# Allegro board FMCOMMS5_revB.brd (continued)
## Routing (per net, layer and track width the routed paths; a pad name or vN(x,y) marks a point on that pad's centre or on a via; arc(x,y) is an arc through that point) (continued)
VDD_AMP_5V: length 43.5
  TOP w0.394: E509.2 C547.2 C548.2 46.72,51.15 47.09,50.79 58.58,50.79 v1(59.37,51.57)
  BOTTOM w0.394: L210.2 13.29,53.53 C254.2 C252.1 C253.2 16.67,54.38 15.19,55.86 v1(10.12,55.86) v1(9.25,55.86) v1(8.37,55.86) ; v1(7.08,87.49) C103.1 C113.2 C112.2 11.3,87.49 L111.2 ; C212.2 C203.1 C213.2 ; L110.2 54.74,124.14 C152.1 C154.2 C153.2 v1(54.75,120.9) ; C213.2 50.99,9.03 v1(51.19,9.23) ; C213.2 50.11,9.04 L211.2 v1(51.12,10.49)
  vias: v1(28.48,8.57) v1(30.23,8.55) v1(31.88,8.55) v1(38.64,8.57) v1(40.04,8.57) v1(41.44,8.57) v1(88.05,39.58) v1(88.05,38.57) v1(88.02,37.52)
VDD_EXT_LO_3P3: length 38
  TOP w0.305: U302.4 24.95,67.48 v3(25.2,67.22) ; v3(28.76,72.73) 28.43,72.4 U302.16 ; v3(37.32,69.15) 37.09,69.38 U307.13 ; C335.1 C334.1 37.93,70.7 38,70.77 C333.1 ; U302.27 v3(21.65,71.4) 21.28,71.4 20.66,72.02 C307.1 ; U307.16 36.99,70.88 v3(37.27,70.6) 37.05,70.38 U307.15 ; v3(30.79,69.08) R317.2 29.7,69.08 29.57,69.2 C308.1 28.68,69.2 28.49,69.4 U302.10 ; v3(31.07,71.36) 30.92,71.21 R318.2
  TOP w0.394: v3(37.32,69.15) C335.1 37.93,68.44 40.44,65.93 40.44,51.63 38.96,50.14 v3(38.55,50.14) ; C306.1 29.12,73.09 v3(28.76,72.73)
  BOTTOM w0.394: R303.1 v3(38.55,50.14)
  vias: v3(70.21,71.13) v3(70.21,70.55) v3(72.78,71.51) v3(72.78,70.8)
VDD_INTERFACE_A: length 50.2
  TOP w0.203: R103.1 26.92,114.77 27.78,113.9 27.78,113.9 27.89,113.8 28.01,113.68 28.01,113.31 27.78,113.09 27.78,112.77 28.01,112.55 28.01,112.18 27.78,111.95 27.78,111.53 28.51,110.81 v2(29.73,110.81)
  TOP w0.305: C612.1 31.91,109.74 31.48,109.74 C613.1 31.06,110.16 30.4,110.16 v2(30.39,110.15) v2(30.03,110.5) v2(29.73,110.81)
  TOP w0.394: v1(53.69,76.66) 53.61,76.74 R511.2 v1(54.19,77.41) ; C612.1 35.19,106.46 v1(35.19,100.01) v1(35.19,99.33) v1(35.19,98.54) ; R507.2 v3(54.2,84.23)
  BOTTOM w0.254: v2(30.39,110.15) v2(30.03,110.5) v2(29.73,110.81) 29.3,111.23 U101.H12
  BOTTOM w0.305: R403.1 79.87,117.14 ; 79.87,121.03 R407.1 79.87,122.05
  BOTTOM w0.394: 79.87,117.14 79.87,121.03 ; v1(66.91,126.28) v1(67.75,126.28) 78.82,126.28 79.87,125.23 79.87,122.05 ; 49.61,72.68 49.6,72.69 C610.1 48.48,72.7 C611.1
  vias: v1(42.71,77.98) v1(44.65,77.35) v1(49.48,77.8) v1(52.35,77.8)
VDD_INTERFACE_B: length 23.6
  TOP w0.229: R203.1 23.25,28.22 23.25,28.41 23.98,29.14 23.98,29.14 26.62,31.78
  TOP w0.305: v1(53.93,69.53) 53.93,69.91 53.65,70.19 R519.2
  TOP w0.394: v2(27.62,30.54) 27.57,30.54 C617.1 26.62,31.49 C616.1 26.2,32.47 v3(25.59,33.08) v3(25.59,33.67) ; R515.2 53.65,64.33 v1(53.88,64.55)
  BOTTOM w0.254: U201.H12 27.2,30.11 v2(27.62,30.54)
  BOTTOM w0.305: 83.37,119.01 R405.1
  BOTTOM w0.394: v1(88.37,119.75) 87.61,120.51 85.71,120.51 84.21,119.01 83.37,119.01 ; v1(49.99,70.24) 49.99,70.42 49.61,70.8 E514.2 49.6,71.32 C614.1 48.46,71.31 C615.1 46.33,71.31
  vias: v1(71.36,61.48) v1(72.3,61.23) v1(73.13,61.23) v1(74.07,61.3) v3(43.44,70.46) v3(44.21,70.47) v3(44.91,70.48) v3(49.28,70.52)
VDD_LNA_3P3: length 27.6
  BOTTOM w0.394: v3(25.04,11.13) C250.1 R212.2 ; v3(6.71,127.34) 7.24,127.87 C148.1 R109.2 ; E504.1 62.6,67.99 C513.1 60.27,67.99 C512.1 58.64,67.99 58.63,68 C510.1 58.12,68.01 C511.1 57.06,66.86 v1(63.6,60.31) v1(64.4,60.31) v1(65.74,60.31) ; R209.2 C248.1 v3(11.11,10.74) ; R112.2 C150.1 v3(11.93,114.91)
  vias: v1(22.45,12.58) v1(22.5,13.82) v1(24.28,12.52) v1(24.33,13.77) v1(25.9,13.85) v1(25.95,12.52)
VDD_RF_SW: length 72.9
  L5_SIG w0.124: v3(23.77,63.61) 23.77,63.53 24.32,62.98 25.36,62.98 25.48,63.11 31.15,63.11 31.4,62.85 32.62,62.85 35.14,65.37 47.45,65.37 50.99,68.9 55.61,68.9 v3(56.95,70.24)
  BOTTOM w0.305: U305.1 19.06,80.46 18.69,80.09 C340.1 16.47,79.64 16.6,79.51 C341.1 16.6,78.8 16.62,78.79 C342.1 ; U306.1 20.94,60.59 21.39,61.05 C343.1 23.68,61.61 23.75,61.68 C345.1 23.75,62.42 23.77,62.44 C344.1 v3(23.77,63.61)
  BOTTOM w0.394: v3(56.95,70.24) 56.85,70.35 C641.1 56.14,70.34 C640.1 55.07,70.35 C639.1 53.6,70.35 53.42,70.52 E1.2 52.92,70.43 53.04,70.31 53.04,69.76 52.92,69.64 52.92,69.3 C638.1 ; v3(23.77,63.61) 22.44,64.95 22.44,65.6 22.94,66.1 22.94,67.68 21.74,68.88 20.85,68.88 20.28,69.46 20.28,70.37 18.17,72.48 18.17,76.39 16.62,77.94 C342.1
VDD_VCO_5V: length 29.7
  TOP w0.305: v1(26.91,77.53) C323.2 26.91,76.19 26.9,76.18 C320.2 26.9,74.76 C309.2 26.89,73.93 ; 26.89,73.93 26.95,73.88 U302.17 ; 26.89,73.93 26.87,73.95 26.2,73.95 25.95,73.71 U302.19 ; v3(25.62,65.39) C317.2 25.62,66.69 25.95,67.03 U302.6
  TOP w0.394: E507.2 47.33,53.89 47.25,53.96 C543.2 C544.2 45.71,54.68 44.64,55.76 v1(42.02,55.76)
  BOTTOM w0.394: v3(25.62,65.39) 25.73,65.5 25.73,67.65 24.49,68.89 24.49,75.12 v1(26.91,77.53)
VDDA_GPO_A: length 15.4
  TOP w0.394: v2(23.64,109.66) 23.63,109.66 C520.1 23.26,109.29 C521.1
  L8_PWR w0.394: 28.61,103.77 26.3,106.08 25,106.08 23.64,107.44 v2(23.64,109.66)
  BOTTOM w0.254: 23.64,109.67 U101.B8
  BOTTOM w0.305: v2(23.64,109.66) 23.64,109.67
  BOTTOM w0.394: E501.2 62.82,73.48 62.8,73.46 C518.1 61.58,73.46 61.56,73.44 C519.1 60.26,73.88 60.74,74.36 v3(61.09,74.36)
VDDA_GPO_B: length 27.3
  TOP w0.394: v2(28.77,24.45) 29.13,24.09 C524.1 29.88,23.32 C525.1 29.88,23.32 33.33,19.88 36.3,19.88 40.95,24.52 v1(40.95,31.31) v1(41.74,31.31)
  BOTTOM w0.254: 28.76,24.45 U201.B8
  BOTTOM w0.305: v2(28.77,24.45) 28.76,24.45
  BOTTOM w0.394: E503.2 63.45,70.16 C523.1 62.33,70.17 C522.1 60.38,70.17 v1(60.26,70.04)
1P3_DIG_A: length 91.9
  TOP w0.305: C589.1 28.16,109.5 v2(28.16,109.53)
  TOP w0.394: v3(32.39,114.72) v3(33.13,114.72) 33.51,114.34 v3(33.84,114.34) 34.4,114.34 L102.1 36.69,114.42 C119.1 36.71,114.42 C118.2 ; C135.1 28.86,120.79 C134.2 ; C134.2 28.41,119.53 v2(28.57,119.53) ; C134.2 27.29,119.22 27.29,119.16 27.29,119.02 26.7,118.43 26.48,118.43 C585.1 26.12,118.07 26.12,117.67 v2(25.9,117.45) ; v3(28.99,117.69) 29.23,117.69 L104.1 ; v1(14.51,117.28) v1(14.51,118.02) v1(14.51,118.73) 14.92,118.73 15.4,118.25 16.36,118.25 C120.2 17.39,117.23 17.39,117.22 C121.1 17.99,116.58 C592.1 18.75,115.78 C593.1 19.77,114.77 20.38,114.77 20.44,114.76 20.49,114.75 20.68,114.75 v2(20.81,114.62) 20.81,114.62 v2(21.38,114.06) v2(21.94,114.62) ; v1(24.7,100.29) v1(25.41,100.29) v1(26.09,100.29) 30.28,100.29 32.98,102.98 32.98,104.71 32.39,105.29 C587.1 31.65,106.04 C586.1 30.87,106.79 C591.1 30.57,107.12 30.31,107.12 C590.1 29.65,107.78 29.65,108.04 C588.1 29.29,108.37 C589.1
  BOTTOM w0.254: v2(20.81,114.62) U101.D2 ; v2(21.94,114.62) U101.E3 ; v2(21.38,114.06) 21.7,114.06 U101.D3 ; v2(28.16,109.53) U101.F12 ; U101.K4 v2(25.9,117.45)
  BOTTOM w0.305: v3(28.99,117.69) 28.99,119.12 28.57,119.53 v2(28.57,119.53) 28.57,119.86 L103.1
  BOTTOM w0.394: L105.1 v1(17.34,108.63) ; v3(42.39,75.95) v3(42.39,75.26) v3(42.39,74.6) 41.59,73.8 41.59,68.72 36.9,64.03 36.9,56.95 41.34,52.51 41.35,52.47 41.35,45.11 41.05,44.81 R325.1 ; L101.1 33.1,115.87 33.1,114.74 v3(33.13,114.72) ; 22.51,105.27 v1(21.61,104.37)
1P3_DIG_B: length 73.8
  TOP w0.356: C220.2 25.08,19.29 C221.1 24.68,19.7 24.65,19.7 24.3,20.05
  TOP w0.394: C218.2 24.66,34.75 24.6,34.75 C219.1 23.64,35.71 23.59,35.71 L202.1 22.88,36.4 21.8,37.48 v1(21.8,39.59) 21.34,39.59 v1(21.01,39.92) ; v2(28.9,28.98) 28.93,28.98 C634.1 29.31,29.38 C635.1 ; v1(23.78,39.18) v1(24.47,39.18) 27.52,36.13 27.52,32.7 27.83,32.39 C636.1 28.57,31.64 C234.2 29.35,30.89 C629.1 30.06,30.16 C635.1 ; C635.1 30.42,30.49 30.67,30.49 C632.1 ; v2(20.98,26.71) 20.98,27.1 C630.1 20.41,27.67 19.7,27.67 19.27,28.1 C633.1 18.88,28.49 18.83,28.49 C637.1 18.12,29.2 18.11,29.2 C235.1 16.48,30.82 v3(16.19,30.82) ; v3(24.06,16.47) v3(24.75,16.47) 25.05,16.47 26.17,17.59 26.17,18.2 C220.2 ; 24.3,20.05 24.23,20.12 24.23,20.52 23.8,20.95 C628.1 23.81,21.08 v2(23.81,21.62) 23.81,21.62 v2(24.37,22.19) v2(23.81,22.75) ; v3(20.74,29.8) 20.74,30.04 L204.1
  BOTTOM w0.254: v2(28.9,28.98) U201.F12 ; U201.K4 v2(20.98,26.71) ; v2(23.81,21.62) U201.D2 ; U201.E3 v2(23.81,22.75) ; U201.D3 v2(24.37,22.19)
  BOTTOM w0.394: L205.1 29.29,18.66 29.29,17.74 v1(29.14,17.59) ; v1(35.09,20.69) 35.09,21.39 33.16,23.32 ; v1(25.94,49.54) 26.22,49.26 30.82,49.26 32.14,47.94 32.14,47.1 33.68,45.56 34.91,45.56 35.52,44.95 37.22,44.95 38.12,44.05 R327.1 ; 17.84,30.11 17.13,30.82 v3(16.19,30.82) ; 22.11,34.37 22.09,34.37 21.34,35.12 21.34,37.91 21.8,38.37 v1(21.8,39.59) 21.34,39.59 v1(21.01,39.92)
  vias: v3(42.43,69.16) v3(42.43,68.48) v3(42.43,67.82)
1P3_RF_A: length 83.7
  TOP w0.305: v2(24.21,109.1) v2(24.77,108.53)
  TOP w0.394: 24.77,117.45 v2(25.34,118.02) 25.34,118.86 25.18,119.02 C572.1 25.18,119.9 25.43,120.15 C574.1 25.43,121.65 C573.1 25.43,122.47 v3(23.27,124.63) v3(23.76,125.11) v3(24.24,125.59) ; 24.77,117.45 24.77,117.85 C575.1 ; 24.77,117.45 v2(24.77,117.45) ; v2(21.38,115.19) v2(21.94,115.76) 21.94,115.8 C570.1 21.06,116.67 21.06,116.73 C571.1 20.48,116.98 19.46,118 17.66,118 16.47,119.19 15.93,119.19 v3(15.78,119.34) v3(16.16,119.72) ; v2(24.21,109.1) 24.21,108.74 C569.1 23.62,108.15 23.56,108.15 C568.1
  L8_PWR w0.394: v1(33.08,100.5) 33.08,101 v1(31.45,102.63) 31.07,102.63 26.91,106.79 25.31,106.79 24.77,107.33 v2(24.77,108.53) v2(24.21,109.1)
  BOTTOM w0.254: v2(21.94,115.76) U101.F2 ; v2(24.77,117.45) 24.77,117.45 U101.J3 ; v2(24.77,108.53) 24.77,108.54 U101.B10 ; U101.B9 24.2,109.1 v2(24.21,109.1) ; v2(21.38,115.19) U101.E2 ; U101.K3 v2(25.34,118.02)
  BOTTOM w0.394: R326.1 39.89,44.67 40.6,45.38 40.6,52.21 35.29,57.52 35.29,63.89 40.47,69.08 40.47,79.49 v3(42.4,81.42) v3(42.4,82.08) v3(42.4,82.77)
1P3_RF_B: length 72.3
  TOP w0.305: v2(29.33,25.02) v2(29.9,25.59) ; v2(20.98,25.58) 20.56,25.58 C607.1 20.21,25.27 20.04,25.11 19.65,25.11 19.49,25.27 19.46,25.27 19.4,25.33 19.37,25.33 C608.1
  TOP w0.394: v3(23.02,16.47) v3(22.28,16.47) v3(21.63,16.47) 21.63,19.72 21.27,20.08 21.27,21.44 C516.1 21.87,22.04 21.92,22.04 C515.1 22.63,22.75 v2(22.67,22.75) v2(23.24,22.19) ; v2(29.33,25.02) 29.69,25.02 C545.1 30.2,24.51 30.2,24.46 C609.1 30.67,23.98 31.83,22.82 31.91,22.82 33.21,21.53 36.63,21.53 39.99,24.88 39.99,37.2 v1(42.12,39.33) v1(43.09,39.33) v1(44.1,39.33) ; C608.1 18.28,24.93 C546.1 17.57,24.24 C517.1 17.55,24.24 16.52,23.2 v3(14.79,23.2) 14.77,23.2 v3(14.33,23.63) v3(13.88,24.09) ; v2(20.41,26.15) v2(20.98,25.58)
  BOTTOM w0.254: v2(29.9,25.59) 29.89,25.58 U201.B10 ; v2(22.67,22.75) U201.F2 ; U201.K3 v2(20.41,26.15) ; U201.B9 29.33,25.02 v2(29.33,25.02) ; v2(20.98,25.58) U201.J3 ; v2(23.24,22.19) U201.E2
  BOTTOM w0.394: TP307.1 25,50.86 25,49.24 27.84,46.4 31.47,46.4 32.98,44.89 34.68,44.89 35.7,43.87 R310.1 35.24,43.3 34.96,43.01 34.96,40.98 35.01,40.93
  vias: v3(42.52,62.36) v3(42.52,61.67) v3(42.52,61.01)
1P3_TX2A_A: length 0.8
  BOTTOM w0.254: U101.A9 U101.A10
1P3_TX2A_B: length 0.8
  BOTTOM w0.254: U201.A9 U201.A10
1P8_CLK: length 82.4
  TOP w0.203: U301.13 v3(18.2,68.24) ; U301.16 v3(18.2,69.74)
  TOP w0.305: U301.10 v3(15.51,66.54) ; U301.22 15.01,72.53 15,72.53 C303.1 ; U301.5 12.53,68.74 v3(12.28,69) 12.52,69.24 U301.4 ; U301.19 v3(17.21,71.49)
  TOP w0.394: Y301.4 Y301.1 C347.1 8.71,75.81 C346.1 8.71,77.55 v1(9.28,78.12) ; C303.1 14.99,73.09 C304.1 C305.1 14.99,75.65 v1(14.69,75.96)
  L5_SIG w0.635: v3(15.51,66.54) 17.59,64.45 28.53,64.45 31.05,66.97 44.71,66.97 v3(45.37,67.63)
  BOTTOM w0.394: C559.1 49.85,67.62 49.84,67.63 C558.1 48.19,67.63 C557.1 48.19,67.25 ; v3(15.51,66.54) 16.5,66.54 v3(18.2,68.24) v3(18.2,69.74) 18.2,70.5 v3(17.21,71.49) 17.21,72.4 15.86,73.75 15.86,74.79 v1(14.69,75.96) 14.69,71.95 13.66,70.92 13.66,69.55 13.11,69 v3(12.28,69) 9.28,72 v1(9.28,78.12)
1P8V: length 42.3
  TOP w0.305: C576.1 56.34,75.63 ; U506.3 55.19,60.74 ; v3(53.91,71.84) 53.86,71.89 53.86,72 53.76,72.1 U505.16 U505.15 ; U505.1 55.17,73.03 ; U504.3 55.18,81.15 ; U504.2 55.18,80.5 ; v1(54.72,65.6) 54.07,66.24 U507.1 ; 55.27,59.44 U506.1 53.95,58.72 ; 53.02,57.56 U506.16 53.74,58.51 ; U504.1 55.18,79.85 ; 53.95,65.32 U507.16 U507.15 ; U505.3 55.17,74.33 ; U507.2 55.21,66.89 ; U506.15 52.37,57.6 ; U504.15 U504.16 53.92,78.92 ; C620.1 56.29,77.38 ; U506.2 55.19,60.09 ; U505.2 55.17,73.68 ; U507.3 55.21,67.54
  TOP w0.394: C555.1 57.76,87.36 ; C560.1 57.76,89.75 ; R506.2 64.73,89.4 ; C594.1 53.09,57.01 ; C556.1 57.76,88.56
  BOTTOM w0.394: E513.1 53.55,71.49 v3(53.91,71.84) ; TP303.1 29.75,54.98 33.33,51.4 R302.2 33.88,50.64 v3(34.4,50.12) R305.1 ; E511.1 50.3,64.96 50.4,64.86
  vias: v1(38.23,63.64) v1(38.21,62.29) v1(39.66,63.67) v1(39.63,62.32) v1(41.18,63.51) v1(41.18,62.37) v1(55.02,64.55) v1(55.13,63.13) v1(55.1,61.84) v1(55.91,64.38) v1(56.01,63.16) v1(55.99,61.84)
3P3V: length 56.9
  TOP w0.394: 75.76,70.35 P501.1 ; P501.1 76.84,71.43 ; P501.1 77.92,70.35 ; P501.1 76.84,69.27 ; C501.1 74.15,77.18
  TOP w0.508: 84.44,56.78 v1(83.28,56.78) ; v3(85.12,128.62) 85.71,128.03 P401.C39 ; v1(84.44,60.21) 84.44,59.32 v1(83.28,59.32) ; v1(84.44,130.16) 84.44,129.27 v1(83.28,129.27) ; P402.C39 v1(86.88,58.05) ; P402.C39 85.69,58.05 v3(85.1,57.46) ; P402.C39 85.71,58.07 v3(85.12,58.66) ; 84.44,124.19 v1(83.28,124.19) ; 84.44,126.73 v1(83.28,126.73) ; P401.C39 v1(86.88,128) ; P401.C39 85.69,128 v3(85.1,127.41) ; 84.44,54.24 v1(83.28,54.24)
  L3_PWR w0.508: P501.1 77.92,70.35 ; P501.1 76.84,69.27 ; P501.1 76.84,71.43 ; P501.1 75.76,70.35
  L8_PWR w0.508: P501.1 77.92,70.35 ; P501.1 75.76,70.35 ; P501.1 76.84,71.43 ; P501.1 76.84,69.27 ; 84.18,127.98 85.43,127.98 85.83,127.57
  BOTTOM w0.394: TP302.1 22.41,53.43 30.11,53.43 v1(32.24,51.3) 32.24,51.24 34.81,48.68 35.26,48.68 35.77,49.19 36.61,49.19 37.03,49.61 R304.1 ; v1(83.28,126.73) 84.06,125.96 84.06,124.97 v1(83.28,124.19) ; P501.1 77.92,70.35 ; P501.1 75.76,70.35 ; P501.1 76.84,69.27 ; P501.1 76.84,71.43
  vias: v1(75.88,72.1) v1(76.89,72.12) v1(77.81,72.12)
5355_LE: length 128.1
  TOP w0.305: U302.3 24.45,67.04 v3(24.52,66.97)
  TOP w0.508: 79.36,121.65 v1(78.2,121.65)
  L6_SIG w0.124: v3(24.52,66.97) 24.52,72.66 24.06,73.12 24.06,80.24 20.78,83.52 20.78,89.58 21.07,89.87 21.07,91.29 19.26,93.1 19.26,108.37 16.77,110.86 16.77,113.2 17.29,113.72 17.29,116 16.85,116.44 16.85,119.1 24.86,127.1 36.04,127.1 36.63,126.51 38.62,126.51 39.4,125.74 41.66,125.74 43.72,127.8 44.33,127.8 45.02,127.11 60,127.11 61.39,125.73 62.12,125.73 64.01,123.84 71.36,123.84 73.54,121.65 v1(78.2,121.65)
  BOTTOM w0.305: v1(78.2,121.65) 78.31,121.54 R407.2
5355_LOCK: length 129
  TOP w0.305: U302.30 v3(21.79,69.9)
  TOP w0.394: R351.1 20.79,69.09 21.6,69.9 v3(21.79,69.9)
  TOP w0.508: 79.36,125.46 v1(78.2,125.46)
  L6_SIG w0.124: v3(21.79,69.9) 20.05,71.64 19.21,71.64 18.4,72.46 18.4,74.26 17.55,75.1 17.55,79.22 16.91,79.86 16.91,106.57 14.61,108.87 14.61,113.4 13.68,114.33 13.68,119.78 23.34,129.44 32.86,129.44 33,129.29 33.87,129.29 34.36,129.78 39.48,129.78 39.93,130.23 59.71,130.23 60.89,129.05 61.52,129.05 62.05,128.52 62.05,127.32 63.9,125.46 v1(78.2,125.46)
5355_REF_N: length 2.2
  TOP w0.203: U302.29 22,70.4 21.93,70.47 20.94,70.47 C319.2
5355_REF_P: length 2.2
  TOP w0.203: U302.28 22,70.9 21.93,70.83 20.94,70.83 C318.2
5355_RF_EN: length 129.7
  TOP w0.305: U302.26 21.9,71.9 v3(21.8,72)
  TOP w0.508: 79.36,117.84 v1(78.2,117.84)
  L6_SIG w0.124: v3(21.8,72) 20.99,72.81 19.26,72.81 18.8,73.27 18.8,74.51 18.06,75.25 18.06,79.45 17.29,80.23 17.29,106.9 15.12,109.08 15.12,120.66 22.54,128.08 33.27,128.08 33.78,128.59 33.78,128.6 34.11,128.93 38.2,128.93 38.89,128.23 41.92,128.23 42.28,128.6 59.43,128.6 61.66,126.37 62.3,126.37 64.2,124.47 71.74,124.47 73.92,122.29 78.49,122.29 79.28,121.5 79.28,118.92 v1(78.2,117.84)
5355_RFOUT_N: length 4
  TOP w0.203: C332.1 31,70.33 30.16,70.33 ; 30.16,70.33 28.47,70.33 28.39,70.4 U302.12 ; 30.16,70.33 R318.1
5355_RFOUT_P: length 4.1
  TOP w0.203: 30.16,69.97 R317.1 ; 30.16,69.97 30.99,69.97 C331.1 ; 30.16,69.97 28.47,69.97 28.39,69.9 U302.11
13617_IN_N: length 1.6
  TOP w0.203: C332.2 32.18,70.3 32.66,70.3 32.73,70.38 U307.6
13617_IN_P: length 1.6
  TOP w0.203: U307.7 32.76,69.88 32.69,69.95 32.15,69.95 R350.2
AUXADC_A: length 87.5
  TOP w0.356: P101.21 68.1,116.68 C143.1
  L6_SIG w0.124: v2(27.03,117.45) 26.89,117.31 26.89,116.83 26.61,116.55 26.16,116.55 26.04,116.66 25.76,116.66 23.86,114.77 23.86,114.32 23.98,114.2 23.98,113.92 23.86,113.8 23.86,113.21 23.98,113.09 23.98,111.61 23.3,110.93 23.3,110.52 23.42,110.4 23.42,110.09 22.63,109.3 19.34,109.3 17.22,111.43 17.22,113.11 17.67,113.56 17.67,118.21 25.35,125.9 35.31,125.9 35.65,125.56 37.65,125.56 38.63,124.57 41.59,124.57 42.71,125.69 44.45,125.69 45.49,126.74 59.77,126.74 63,123.51 63.53,123.51 66.94,120.1 66.94,118.45 68.09,117.3 P101.21
  BOTTOM w0.254: v2(27.03,117.45) 27.03,116.89 U101.L5
AUXADC_B: length 121
  TOP w0.356: P201.21 68.33,46.71 C243.1
  L6_SIG w0.124: P201.21 68.35,47.49 67.15,48.69 67.15,49.87 64.57,52.45 64.57,53.86 62.39,56.05 59.41,56.05 59.01,56.44 23.19,56.44 13.88,47.13 13.88,39.15 12.95,38.23 12.95,34.27 12.5,33.82 12.5,26.48 20.28,18.71 25.81,18.71 28.7,21.59 28.7,23.88 28.34,24.23 28.06,24.23 27.89,24.06 27.55,24.06 26.79,24.82 25.77,24.82 22.39,28.21 21.85,28.21 21.55,27.9 21.04,27.9 v2(20.98,27.84)
  BOTTOM w0.254: v2(20.98,27.84) U201.L5
AUXDAC1_A: length 60.2
  TOP w0.356: C144.1 P101.22
  L5_SIG w0.124: v3(59.11,122.9) 61.64,120.37 66.95,120.37 P101.22
  L6_SIG w0.124: v3(59.11,122.9) 58.53,123.48 45.55,123.48 44.52,122.44 36.1,122.44 35.84,122.18 31.89,122.18 31.01,123.06 26.38,123.06 20.15,116.83 20.15,114.45 19.9,114.2 19.9,113.92 20.24,113.58 v2(20.24,112.93)
  BOTTOM w0.254: U101.B3 v2(20.24,112.93)
AUXDAC1_B: length 92.5
  TOP w0.356: P201.22 68.36,49.28 C244.1
  L5_SIG w0.124: v3(60.07,52.03) 62.14,52.03 62.48,51.68 65.94,51.68 P201.22
  L6_SIG w0.124: v2(25.5,21.06) 24.85,21.06 24.51,20.71 24.23,20.71 24.11,20.83 21.68,20.83 18.74,23.77 18.74,23.77 16.72,25.79 16.72,36.79 16.04,37.48 16.04,47.1 22.93,53.99 57.79,53.99 59.75,52.03 v3(60.07,52.03)
  BOTTOM w0.254: U201.B3 v2(25.5,21.06)
AUXDAC2_A: length 62.9
  TOP w0.356: P101.23 70.62,116.68 C145.1
  L5_SIG w0.124: P101.23 69.35,117.97 69.35,119.93 68.49,120.79 62.21,120.79 59.52,123.48 58.76,123.48 v3(58.1,122.82)
  L6_SIG w0.124: v2(20.81,113.49) 20.81,114.14 21.15,114.48 21.15,114.77 20.94,114.98 20.94,117.08 25.5,121.65 35.85,121.65 36.14,121.95 57.22,121.95 v3(58.1,122.82)
  BOTTOM w0.254: v2(20.81,113.49) U101.C3
AUXDAC2_B: length 95.2
  TOP w0.394: P201.23 70.91,46.71 C245.1
  L5_SIG w0.124: P201.23 69.53,48.1 69.53,50.1 67.53,52.1 62.73,52.1 62.2,52.63 58.62,52.63 v3(58.43,52.44)
  L6_SIG w0.124: v2(24.94,21.62) 24.29,21.62 23.95,21.96 23.66,21.96 23.45,21.75 21.3,21.75 17.16,25.89 17.16,37 16.44,37.71 16.44,46.97 23.07,53.6 57.26,53.6 v3(58.43,52.44)
  BOTTOM w0.254: v2(24.94,21.62) U201.C3
CAL_SW_1: length 134
  TOP w0.394: 84.44,111.49 v1(83.28,111.49)
  L5_SIG w0.097: v3(19.82,83.63) 19.82,82.82 21.12,81.52 21.12,75.47 20.62,74.97 18.5,74.97 17.71,74.18 17.71,67.86 19.67,65.9 22.38,65.9 22.77,66.28 28.74,66.28 39.3,76.85 42.43,76.85 44.2,78.63 53.98,78.63 55.86,80.51 87.38,80.51 88.15,81.27 88.15,103.33 87.1,104.38 86.39,104.38 85.66,105.12 85.66,110.58 84.23,112 83.79,112 v1(83.28,111.49)
  BOTTOM w0.203: v3(19.82,83.63) 19.72,83.53 R319.1 19.71,83.01 U305.2
CAL_SW_2: length 133.4
  TOP w0.394: 84.44,112.76 v1(83.28,112.76)
  L5_SIG w0.097: v3(20.3,57.54) 18.83,57.54 13.34,63.03 13.34,66.76 13.91,67.34 16.99,67.34 18.78,65.55 22.56,65.55 22.91,65.9 28.74,65.9 39.43,76.59 42.53,76.59 44.31,78.37 54.08,78.37 55.96,80.25 87.49,80.25 88.4,81.17 88.4,103.44 87.21,104.64 86.5,104.64 85.91,105.22 85.91,110.68 84.34,112.26 83.57,112.26 83.28,112.55 v1(83.28,112.76)
  BOTTOM w0.203: U306.2 20.29,58.12 R320.1 v3(20.3,57.54)
CAL_SW_3: length 1.2
  TOP w0.394: 84.44,41.54 v1(83.28,41.54)
CAL_SW_4: length 1.2
  TOP w0.394: 84.44,42.81 v1(83.28,42.81)
CLK_OUT_A: length 38.3
  TOP w0.394: v3(39.23,119.19) 41.36,121.33 53.35,121.33 53.93,121.9 C142.1
  L5_SIG w0.124: v3(39.23,119.19) 38.25,118.21 28.27,118.21 27.8,117.74 26.69,116.63 26.69,115.98 v2(25.9,115.19)
  BOTTOM w0.254: v2(25.9,115.19) U101.J6
CLK_OUT_B: length 120
  TOP w0.394: v3(59.63,54.6) 60.74,53.49 C242.1
  L5_SIG w0.124: v3(59.63,54.6) 56.19,58.04 21.87,58.04 17.4,53.57 15.29,53.57 11.95,50.23 11.95,42.82 8.31,39.19 8.31,35.45 7.79,34.92 7.79,28.52 18.38,17.92 19.99,17.92 20.41,18.34 27.96,18.34 30.34,20.71 30.34,24.65 29.07,25.92 28.76,25.92 28.64,25.81 28.19,25.81 28.07,25.92 27.62,25.92 27.51,25.81 27.06,25.81 26.38,26.49 25.93,26.49 25.73,26.29 25.16,26.29 24.71,26.74 24.71,26.85 24.51,27.05 23.79,27.05 23.47,26.74 23.44,26.71 v2(23.24,26.71)
  BOTTOM w0.254: v2(23.24,26.71) U201.J6
CTRL_IN0_A: length 101.3
  TOP w0.356: P101.20 65.54,119.24 R107.1
  TOP w0.394: 84.44,107.68 v1(83.81,108.32)
  L6_SIG w0.124: v1(83.81,108.32) 82.74,109.39 82.74,112.62 81.32,114.04 79.15,114.04 77.93,115.25 67.75,115.25 66.75,116.25 66.75,118.03 P101.20 65.42,119.23 61.86,122.8 61.86,123.46 58.96,126.36 46.06,126.36 44.88,125.17 42.97,125.17 41.79,123.99 36.76,123.99 36.22,124.53 34.67,124.53 33.87,125.33 25.33,125.33 18.05,118.05 18.05,111.92 18.15,111.81 18.15,111.17 19.65,109.68 21.88,109.68 22.85,110.65 22.85,110.94 22.73,111.06 22.73,111.37 23.41,112.06 23.41,112.5 23.21,112.7 22.77,112.7 22.57,112.51 22.09,112.51 v2(21.94,112.36)
  BOTTOM w0.254: v2(21.94,112.36) U101.C5
CTRL_IN0_B: length 136.5
  TOP w0.356: R207.1 65.82,51.5 65.82,49.28 P201.20
  TOP w0.394: 84.44,37.73 v1(83.81,38.36)
  L6_SIG w0.124: v2(26.07,22.75) 25.92,22.9 25.92,23.38 25.73,23.58 25.73,24.03 25.93,24.23 26.38,24.23 27.29,23.31 27.29,23.18 27.54,22.93 27.54,22.61 27.26,22.33 27.26,21.65 27.49,21.41 27.49,21.02 25.75,19.28 20.59,19.28 14.18,25.7 14.18,34.63 14.49,34.94 14.49,47.15 22.5,55.17 23.26,55.17 54.1,55.17 54.98,56.05 58.45,56.05 59.01,55.49 59.01,54.45 60.01,53.45 61.63,53.45 P201.20 67.09,48 67.09,46.29 67.93,45.45 80.74,45.45 81.53,44.66 83.37,44.66 85.6,42.43 85.6,38.13 85.32,37.84 84.33,37.84 v1(83.81,38.36)
  BOTTOM w0.254: v2(26.07,22.75) U201.C5
CTRL_IN1_A: length 97.8
  TOP w0.356: P101.19 65.56,116.69 R106.1
  TOP w0.394: v1(85.08,108.32) 84.44,108.95
  L5_SIG w0.124: P101.19 67.07,115.17 75.49,115.17 76.42,116.1 79.57,116.1 80.73,114.95 80.73,114.59 82.61,112.71 82.61,110.05 83.57,109.08 84.32,109.08 v1(85.08,108.32)
  L6_SIG w0.124: v2(22.51,111.8) 22.46,111.75 22.46,111.27 22.08,110.89 21.6,110.89 21.2,110.49 20.17,110.49 20.04,110.62 19.32,110.62 18.69,111.25 18.69,111.91 18.43,112.18 18.43,117.9 25.48,124.96 33.56,124.96 34.38,124.13 36.06,124.13 36.58,123.61 43.95,123.61 46.31,125.97 58.76,125.97 61.27,123.46 61.27,122.73 64.18,119.82 64.18,118.64 65.55,117.27 P101.19
  BOTTOM w0.254: v2(22.51,111.8) U101.C6
CTRL_IN1_B: length 133.8
  TOP w0.394: R206.1 65.82,46.72 P201.19 ; v1(85.08,38.36) 84.44,39
  L5_SIG w0.124: v2(26.63,23.32) 27.15,23.32 27.49,23.66 27.84,23.66 28.57,22.94 28.57,22.1 26.07,19.59 20.15,19.59 19.05,20.7 18.64,20.7 12.43,26.91 12.43,30.21 11.36,31.28 11.36,31.76 11.4,31.8 11.4,36.91 10.9,37.42 10.9,38.05 11.55,38.71 11.55,40.39 13.29,42.12 13.29,46.57 21.72,55 53.93,55 57.95,50.99 63.41,50.99 64.57,49.82 64.57,47.97 P201.19
  L6_SIG w0.124: v1(85.08,38.36) 85.08,41.89 83.58,43.39 80.24,43.39 78.55,45.07 67.47,45.07 P201.19
  BOTTOM w0.254: U201.C6 v2(26.63,23.32)
CTRL_IN2_A: length 89.3
  TOP w0.356: R105.1 63.05,119.27 P101.18
  TOP w0.394: 79.36,114.03 v1(78.2,114.03)
  L6_SIG w0.124: v2(23.07,112.36) 22.89,112.18 22.31,112.18 21.58,111.45 20.84,111.45 20.55,111.74 20.27,111.74 20.15,111.62 19.7,111.62 18.91,112.41 18.91,116.68 19.07,116.84 19.07,117.02 18.85,117.24 18.85,117.42 19.29,117.87 19.47,117.87 19.7,117.65 19.87,117.65 20.33,118.1 20.33,118.27 19.94,118.66 19.94,118.83 20.39,119.28 20.57,119.28 20.95,118.9 21.13,118.9 21.58,119.35 21.58,119.53 21.2,119.91 21.2,120.08 21.65,120.54 21.82,120.54 22.21,120.15 22.38,120.15 22.83,120.6 22.83,120.78 22.45,121.16 22.45,121.34 22.9,121.79 23.08,121.79 23.46,121.41 23.64,121.41 24.37,122.14 24.37,123.02 25.82,124.48 32.17,124.48 32.91,123.74 35.92,123.74 36.42,123.23 44.11,123.23 46.42,125.54 58.52,125.54 60.75,123.32 60.75,122.34 63.01,120.08 P101.18 64.4,117.85 64.4,116.14 65.72,114.82 77.38,114.82 78.16,114.03 v1(78.2,114.03)
  BOTTOM w0.254: v2(23.07,112.36) U101.D6
CTRL_IN2_B: length 124.4
  TOP w0.394: P201.18 63.28,49.28 R205.1 ; 79.36,44.08 v1(78.2,44.08)
  L6_SIG w0.124: v1(78.2,44.08) 77.63,44.65 66.11,44.65 64.52,46.24 64.52,48.02 P201.18 63.27,50.71 60.91,53.07 59.85,53.07 58.16,54.76 58.16,55.54 58.04,55.66 57.4,55.66 57.27,55.54 57.27,54.94 57.15,54.81 56.51,54.81 56.39,54.94 56.39,55.54 56.26,55.66 55.35,55.66 54.48,54.79 22.66,54.79 14.87,47 14.87,35.45 15.61,34.71 15.61,32.84 14.55,31.79 14.55,26.87 15.37,26.05 15.37,25.87 15.05,25.55 15.05,25.38 15.5,24.92 15.68,24.92 16,25.25 16.17,25.25 16.96,24.46 16.96,24.29 16.65,23.98 16.65,23.81 17.11,23.36 17.28,23.36 17.58,23.66 17.76,23.66 18.21,23.21 18.21,23.03 17.91,22.73 17.91,22.55 18.36,22.1 18.54,22.1 18.84,22.41 19.01,22.41 19.47,21.95 19.47,21.78 19.16,21.48 19.16,21.3 19.61,20.85 19.79,20.85 20.09,21.15 20.27,21.15 20.72,20.7 20.72,20.53 20.5,20.31 20.5,20.13 20.95,19.68 21.13,19.68 21.35,19.9 21.52,19.9 21.75,19.67 25.23,19.67 26.69,21.14 26.69,21.36 26.98,21.65 26.98,22.4 26.25,23.12 26.25,23.7 v2(26.07,23.88)
  BOTTOM w0.254: v2(26.07,23.88) U201.D6
CTRL_IN3_A: length 89.7
  TOP w0.356: R104.1 63.01,116.69 P101.17
  TOP w0.394: v1(80,114.67) 79.36,115.3
  L5_SIG w0.124: v1(80,114.67) 78.94,115.73 76.68,115.73 75.75,114.79 64.91,114.79 P101.17
  L6_SIG w0.124: P101.17 61.76,117.95 61.76,119.98 60.19,121.54 60.19,123.09 59.35,123.93 57.61,123.93 57.44,124.11 57.44,124.9 57.28,125.06 56.8,125.06 56.62,124.88 56.62,124.07 56.49,123.93 55.82,123.93 55.69,124.06 55.69,124.96 55.57,125.09 54.93,125.09 54.81,124.96 54.81,124.24 54.68,124.11 54.05,124.11 53.92,124.24 53.92,124.85 53.75,125.02 46.44,125.02 44.27,122.85 35.98,122.85 35.68,122.56 33.54,122.56 32.05,124.05 30.64,124.05 30.52,123.92 30.52,123.59 30.39,123.47 29.76,123.47 29.63,123.59 29.63,123.92 29.51,124.05 28.87,124.05 28.75,123.92 28.75,123.59 28.62,123.47 27.98,123.47 27.86,123.59 27.86,123.92 27.74,124.05 26.81,124.05 19.34,116.57 19.34,112.69 19.72,112.3 20.29,112.3 20.58,112.02 20.95,112.02 21.86,112.93 v2(22.51,112.93)
  BOTTOM w0.254: v2(22.51,112.93) U101.D5
CTRL_IN3_B: length 130.1
  TOP w0.356: R204.1 63.28,46.72 P201.17
  TOP w0.394: v1(80,44.71) 79.36,45.35
  L5_SIG w0.124: P201.17 64.79,45.21 76.28,45.21 76.85,45.78 80.81,45.78 80.94,45.91 80.94,48.17 81.07,48.29 82.59,48.29 82.72,48.17 82.72,44.84 82.59,44.71 v1(80,44.71)
  L6_SIG w0.124: P201.17 61.93,48.07 61.93,51.3 60.64,52.59 59.75,52.59 57.93,54.41 22.82,54.41 15.43,47.03 15.43,35.47 15.56,35.34 16.17,35.34 16.29,35.21 16.29,32.05 16.17,31.92 15.22,31.92 14.93,31.63 14.93,28.78 15.12,28.59 16.2,28.59 16.32,28.46 16.32,27.83 16.2,27.7 15.31,27.7 15.18,27.58 15.18,26.94 15.31,26.82 16.2,26.82 16.32,26.69 16.32,25.63 21.81,20.15 25.17,20.15 26.41,21.39 26.41,21.76 25.5,22.67 v2(25.5,23.32)
  BOTTOM w0.254: v2(25.5,23.32) U201.D5
CTRL_OUT0_A: length 88.8
  TOP w0.394: P401.H22 v1(78.2,106.41)
  L5_SIG w0.124: P101.11 57.67,114.41 76.1,114.41 77.03,115.34 78.63,115.34 79.43,114.54 79.43,114.47 81.33,112.57 82.23,111.67 82.23,109.23 83.75,107.71 83.75,106.22 83.47,105.94 83.42,105.94 82.64,105.17 82.64,104.06 81.99,103.4 81.21,103.4 v1(78.2,106.41)
  L6_SIG w0.124: P101.11 54.24,117.85 54.24,120.51 53.86,120.89 39.35,120.89 38.29,119.83 31.37,119.83 30.31,120.89 26.58,120.89 22.17,116.48 22.17,116.18 22.42,115.93 22.42,115.61 22.17,115.36 22.17,114.88 22.28,114.77 22.28,114.48 22.17,114.37 22.17,113.72 v2(21.94,113.49)
  BOTTOM w0.254: v2(21.94,113.49) U101.D4
CTRL_OUT0_B: length 119.3
  TOP w0.394: P402.H22 v1(78.2,36.46)
  L5_SIG w0.124: P201.11 57.6,44.78 76.49,44.78 77.12,45.4 78.62,45.4 79.49,44.53 79.49,44.34 81.35,42.48 81.82,42.01 82.03,42.01 82.66,41.37 82.66,38.82 83.83,37.66 83.83,35.2 82.06,33.43 81.53,33.43 78.51,36.46 v1(78.2,36.46)
  L6_SIG w0.124: v2(24.94,22.75) 24.71,22.98 24.07,22.98 23.95,23.09 23.66,23.09 23.55,22.98 23.07,22.98 22.82,23.23 22.5,23.23 22.25,22.98 21.96,22.98 18.19,26.74 18.19,46.11 18.2,46.12 18.2,47.65 23.39,52.84 52.37,52.84 54.47,50.74 54.47,47.91 P201.11
  BOTTOM w0.254: v2(24.94,22.75) U201.D4
CTRL_OUT1_A: length 83.8
  TOP w0.394: P401.H23 v1(78.2,107.68)
  L5_SIG w0.124: P101.10 54.21,117.87 54.21,116.04 56.22,114.03 76.44,114.03 77.35,114.95 78.48,114.95 79.05,114.38 79.05,114.32 80.95,112.41 81.81,111.55 81.81,109.05 82.72,108.14 82.72,105.96 82.27,105.5 82.27,104.95 81.99,104.67 81.22,104.67 78.21,107.68 v1(78.2,107.68)
  L6_SIG w0.124: v2(22.51,114.06) 22.72,114.27 22.72,114.77 22.95,115 22.95,115.4 22.73,115.61 22.73,115.99 27.15,120.41 29.85,120.41 30.87,119.39 38.49,119.39 39.5,120.41 51.67,120.41 P101.10
  BOTTOM w0.254: v2(22.51,114.06) U101.E4
CTRL_OUT1_B: length 114.2
  TOP w0.394: P402.H23 v1(78.2,37.73)
  L5_SIG w0.124: v1(78.2,37.73) 78.2,37.63 81.12,34.7 82.12,34.7 82.74,35.33 82.74,38.17 82.28,38.63 82.28,40.15 81.31,41.12 81.31,41.98 80.98,42.32 79.12,44.18 79.12,44.37 78.52,44.97 77.45,44.97 76.76,44.27 56.15,44.27 54.35,46.08 54.35,48.04 P201.10
  L6_SIG w0.124: v2(24.37,23.32) 24.16,23.53 23.66,23.53 23.43,23.76 23.03,23.76 22.82,23.54 22.44,23.54 18.58,27.41 18.58,47.5 23.52,52.44 50.71,52.44 53.11,50.03 P201.10
  BOTTOM w0.254: v2(24.37,23.32) U201.E4
CTRL_OUT2_A: length 77.4
  TOP w0.394: P401.G21 v1(81.8,105.14)
  L5_SIG w0.124: P101.9 52.85,115.83 56.03,112.65 75.64,112.65 77.49,114.5 78.39,114.5 78.67,114.23 78.67,114.16 80.57,112.26 81.43,111.4 81.43,108.85 82.32,107.96 82.32,106.1 81.8,105.57 v1(81.8,105.14)
  L6_SIG w0.124: P101.9 51.57,117.97 41.64,117.97 40.98,118.63 29.22,118.63 29.09,118.76 29.09,119.9 28.96,120.03 27.9,120.03 27.77,119.9 27.77,118.99 27.64,118.86 26.82,118.86 23.45,115.49 23.45,114.52 23.07,114.14 v2(23.07,113.49)
  BOTTOM w0.254: v2(23.07,113.49) U101.E5
CTRL_OUT2_B: length 107.4
  TOP w0.394: 80.63,35.19 v1(81.8,35.19)
  L5_SIG w0.124: v1(81.8,35.19) 82.35,35.74 82.35,38.03 81.9,38.47 81.9,39.98 80.93,40.95 80.93,41.83 80.6,42.16 78.74,44.02 78.74,44.22 78.39,44.56 77.63,44.56 76.96,43.9 54.93,43.9 53.11,45.71 P201.9
  L6_SIG w0.124: v2(24.94,23.88) 24.29,23.88 23.95,24.23 22.96,24.23 19.11,28.08 19.11,47.44 23.73,52.06 33.79,52.06 34.93,50.92 39.88,50.92 40.32,50.48 44.54,50.48 45.18,51.12 51.26,51.12 51.72,50.66 51.72,48.12 P201.9
  BOTTOM w0.254: v2(24.94,23.88) U201.E5
CTRL_OUT3_A: length 85.2
  TOP w0.394: P401.G22 v1(81.8,106.41)
  L5_SIG w0.124: v1(81.8,106.41) 81.05,107.16 81.05,110.69 78.51,113.23 76.98,113.23 76.02,112.27 55.49,112.27 51.49,116.27 51.49,118.05 P101.8 50.31,120.55 47.1,123.76 43.19,123.76 42.82,124.13 34.18,124.13 33.36,124.96 27.74,124.96 21.32,118.54 21.32,115.73 21.72,115.33 21.72,115.05 21.56,114.89 21.56,114.36 21.72,114.2 21.72,113.92 21.56,113.76 21.56,113.32 21.79,113.09 22.14,113.09 22.36,113.31 22.77,113.31 23.16,112.93 v2(23.64,112.93)
  BOTTOM w0.254: v2(23.64,112.93) 24.2,112.93 U101.E6
CTRL_OUT3_B: length 117.9
  TOP w0.394: P402.G22 v1(81.8,36.46)
  L5_SIG w0.124: v2(25.5,24.45) 25.5,23.97 25.12,23.58 25.12,23.21 25.28,23.05 25.28,22.61 25.08,22.41 24.8,22.41 24.68,22.53 24.23,22.53 24.06,22.36 23.55,22.36 23.38,22.53 23.1,22.53 22.73,22.16 19.72,22.16 17.58,24.3 17.58,25.42 14.89,28.11 14.89,31.74 15.43,32.28 15.43,33.33 15.2,33.57 15.2,46.24 22.44,53.48 48.17,53.48 48.62,53.02 48.62,51.22 P201.8 50.57,49.17 51.83,47.91 51.83,45.97 55.02,42.79 77.07,42.79 77.81,43.52 78.43,43.52 80.55,41.4 80.55,40.8 81.24,40.11 81.24,37.02 v1(81.8,36.46)
  BOTTOM w0.254: U201.E6 25.5,25.02 v2(25.5,24.45)
CTRL_OUT4_A: length 77.1
  TOP w0.394: 79.36,110.22 v1(78.2,110.22)
  L5_SIG w0.124: v2(24.2,113.49) 23.72,113.49 23.38,113.83 22.87,113.83 22.71,113.67 22.28,113.67 22.1,113.85 22.1,114.3 22.28,114.48 22.28,114.77 22.1,114.95 22.1,115.43 22.28,115.61 22.28,115.9 22.13,116.05 22.13,118.81 27.38,124.07 32.41,124.07 32.77,123.71 42.68,123.71 43.01,123.38 46.9,123.38 49.03,121.25 49.03,118.78 49.54,118.28 49.54,117.46 P101.7 55.11,111.89 76.18,111.89 76.39,112.11 78.39,112.11 78.75,111.75 78.75,110.77 v1(78.2,110.22)
  BOTTOM w0.254: v2(24.2,113.49) U101.F6
CTRL_OUT4_B: length 107.9
  TOP w0.394: 79.36,40.27 v1(78.2,40.27)
  L5_SIG w0.124: v1(78.2,40.27) 78.71,40.78 78.71,41.72 78.28,42.15 54.47,42.15 50.57,46.05 P201.7 50.57,47.62 49.32,48.87 49.32,49.72 45.98,53.07 22.83,53.07 15.63,45.86 15.63,35.69 16.76,34.56 16.76,26.87 17.96,25.68 17.96,25.58 17.96,25.58 17.96,25.26 17.96,25.26 17.96,24.46 19.8,22.62 22.06,22.62 22.53,23.09 22.98,23.09 23.1,22.98 23.55,22.98 23.66,23.09 24.11,23.09 24.23,22.98 24.51,22.98 24.71,23.18 24.71,23.62 24.6,23.74 24.6,24.19 24.94,24.53 v2(24.94,25.02)
  BOTTOM w0.254: v2(24.94,25.02) U201.F6
CTRL_OUT5_A: length 76.7
  TOP w0.394: 79.36,111.49 v1(78.2,111.49)
  L5_SIG w0.124: v1(78.2,111.49) 53.78,111.49 48.98,116.29 48.98,118.02 P101.6 47.77,121.03 46.25,122.56 42.05,122.56 41.92,122.68 41.92,123.2 41.8,123.32 41.16,123.32 41.04,123.2 41.04,122.68 40.91,122.56 40.28,122.56 40.15,122.68 40.15,123.2 40.03,123.32 39.39,123.32 39.27,123.2 39.27,122.68 39.14,122.56 38.5,122.56 38.38,122.68 38.38,123.2 38.25,123.32 37.62,123.32 37.49,123.2 37.49,122.68 37.37,122.56 36.73,122.56 36.61,122.68 36.61,123.2 36.48,123.32 35.84,123.32 35.72,123.2 35.72,122.68 35.59,122.56 31.57,122.56 30.94,123.18 27.03,123.18 22.66,118.81 22.66,116.65 22.85,116.46 22.85,116.18 22.66,115.99 22.66,115.52 22.85,115.33 22.85,115.05 22.66,114.86 22.66,114.51 22.91,114.26 23.44,114.26 v2(23.64,114.06)
  BOTTOM w0.254: v2(23.64,114.06) U101.F5
CTRL_OUT5_B: length 107.9
  TOP w0.394: 79.36,41.54 v1(78.2,41.54)
  L5_SIG w0.124: v1(78.2,41.54) 78.07,41.67 53.14,41.67 49.27,45.54 49.27,48.04 P201.6 48.03,50.16 45.5,52.69 23.01,52.69 16.42,46.09 16.42,41.57 16.54,41.45 17.69,41.45 17.82,41.32 17.82,40.68 17.69,40.56 16.54,40.56 16.42,40.43 16.42,39.8 16.54,39.67 17.69,39.67 17.82,39.55 17.82,38.91 17.69,38.79 16.54,38.79 16.42,38.66 16.42,37.63 16.59,37.46 17.13,37.46 17.25,37.33 17.25,26.97 18.34,25.88 18.34,25.74 18.34,25.74 18.34,25.11 18.34,24.62 19.45,23.51 21.82,23.51 21.97,23.66 22.25,23.66 22.45,23.46 22.9,23.46 23.1,23.66 23.38,23.66 23.5,23.54 23.95,23.54 24.17,23.76 24.17,24.25 v2(24.37,24.45)
  BOTTOM w0.254: v2(24.37,24.45) 24.37,25.02
CTRL_OUT6_A: length 77.2
  TOP w0.394: v1(80,109.59) P401.G24
  L5_SIG w0.124: v2(23.07,114.62) 23.41,114.97 23.41,115.9 23.3,116.02 23.3,116.46 23.41,116.58 23.41,117.03 23.41,117.03 23.41,117.36 23.29,117.49 23.29,118.9 25.74,121.35 26.65,121.35 26.77,121.47 26.77,122.32 26.9,122.45 27.53,122.45 27.66,122.32 27.66,121.41 27.79,121.29 29.06,121.29 29.18,121.41 29.18,122.64 29.31,122.77 29.94,122.77 30.07,122.64 30.07,121.43 30.2,121.31 31.04,121.31 31.17,121.43 31.17,121.69 31.61,122.14 45.85,122.14 46.52,121.48 46.52,118.76 47.26,118.01 47.26,117.2 P101.5 47.77,116.16 52.81,111.11 77.17,111.11 77.29,110.99 77.29,109.72 77.42,109.59 v1(80,109.59)
  BOTTOM w0.254: v2(23.07,114.62) U101.F4
CTRL_OUT6_B: length 107.8
  TOP w0.394: v1(80,39.63) P402.G24
  L5_SIG w0.124: v2(23.81,23.88) 23.46,24.23 22.53,24.23 22.42,24.11 21.97,24.11 21.85,24.23 20.91,24.23 20.73,24.04 19.45,24.04 18.71,24.77 18.71,26.13 17.71,27.14 17.71,36.16 18.3,36.74 18.3,42.02 18.17,42.14 16.93,42.14 16.81,42.27 16.81,42.9 16.93,43.03 18.62,43.03 18.74,43.16 18.74,43.79 18.62,43.91 16.93,43.91 16.81,44.04 16.81,44.68 16.93,44.8 18.17,44.8 18.3,44.93 18.3,47.41 23.2,52.31 44.87,52.31 46.8,50.37 46.8,48.77 48.03,47.54 P201.5 48.03,45.82 53.15,40.71 76.89,40.71 78.1,39.5 79.87,39.5 v1(80,39.63)
  BOTTOM w0.254: v2(23.81,23.88) U201.F4
CTRL_OUT7_A: length 79
  TOP w0.394: v1(80,110.86) P401.G25
  L5_SIG w0.124: v2(24.2,115.76) 24.02,115.94 24.02,116.49 23.8,116.71 23.8,118.09 26.6,120.89 31.25,120.89 31.82,121.46 36.32,121.46 36.44,121.33 36.44,121.02 36.57,120.89 37.68,120.89 37.82,121.03 37.82,121.54 37.94,121.67 38.58,121.67 38.7,121.54 38.7,121.03 38.83,120.9 39.46,120.9 39.59,121.03 39.59,121.54 39.7,121.66 45.3,121.66 45.61,121.35 45.61,119.61 P101.4 45.23,118.7 46.57,117.36 46.57,116.14 47.33,115.38 47.76,115.38 53.22,109.92 74.81,109.92 74.94,109.79 74.94,108.42 75.06,108.29 79.36,108.29 79.48,108.17 79.48,107.05 79.61,106.92 80.5,106.92 80.63,107.05 80.63,110.23 v1(80,110.86)
  BOTTOM w0.254: U101.G4 v2(24.2,115.76)
CTRL_OUT7_B: length 109
  TOP w0.394: v1(80,40.9) P402.G25
  L5_SIG w0.124: v1(80,40.9) 80,40.4 80.64,39.76 80.64,36.96 80.51,36.83 79.62,36.83 79.5,36.96 79.5,38.21 79.37,38.34 77.63,38.34 75.88,40.09 52.71,40.09 46.67,46.13 46.67,48.1 P201.4 45.49,49.42 43.98,50.94 34.4,50.94 33.41,51.93 23.45,51.93 19.14,47.61 19.14,41.09 19.26,40.96 19.99,40.96 20.11,40.84 20.11,40.2 19.99,40.08 19.26,40.08 19.14,39.95 19.14,39.32 19.26,39.19 20.78,39.19 20.91,39.07 20.91,38.43 20.78,38.3 19.26,38.3 19.14,38.18 19.14,36.79 18.17,35.83 18.17,27.22 19.51,25.88 19.51,25.44 20.34,24.61 21.72,24.61 21.94,24.83 22.49,24.83 v2(22.67,25.02)
  BOTTOM w0.254: U201.G4 v2(22.67,25.02)
DATA_CLK_N_A: length 84.9
  TOP w0.203: 80.63,87.36 v1(80,86.73)
  L5_SIG w0.097: v2(28.73,111.23) 28.7,111.23 28.55,111.08 28.55,110.74 28.69,110.6 29.26,110.6 30.85,109.01 30.85,98.53 42.17,87.21 67.45,87.21 67.55,87.31 67.55,90.67 67.83,90.94 69.91,90.94 70.19,90.67 70.19,87.31 70.28,87.21 72.22,87.21 72.32,87.31 72.32,90.64 72.59,90.91 74.68,90.91 74.95,90.64 74.95,87.31 75.05,87.21 77.44,87.21 78.68,85.97 80.15,85.97 80.26,86.09 80.26,86.46 v1(80,86.73)
  BOTTOM w0.203: U101.H11 v2(28.73,111.23)
DATA_CLK_N_B: length 84.8
  TOP w0.203: 80.63,17.41 v1(80,16.77)
  L5_SIG w0.097: v2(27.2,29.54) 27.3,29.54 28.28,30.52 33.81,30.52 47.28,17.04 47.46,17.04 48.43,18.01 48.43,18.19 42.82,23.79 42.82,24.18 43.94,25.3 44.33,25.3 52.24,17.39 73.07,17.39 73.17,17.49 73.17,19.73 73.44,20.01 75.02,20.01 75.3,19.73 75.3,17.49 75.39,17.39 77.33,17.39 78.7,16.02 80.05,16.02 80.17,16.15 80.17,16.65 80.05,16.77 v1(80,16.77)
  BOTTOM w0.203: U201.H11 v2(27.2,29.54)
DATA_CLK_P_A: length 84.9
  TOP w0.203: 80.63,86.09 v1(80,85.46)
  L5_SIG w0.097: v1(80,85.46) 79.74,85.72 78.58,85.72 77.34,86.96 74.94,86.96 74.7,87.2 74.7,90.53 74.57,90.66 72.7,90.66 72.57,90.53 72.57,87.2 72.32,86.96 70.18,86.96 69.93,87.2 69.93,90.56 69.81,90.69 67.93,90.69 67.8,90.56 67.8,87.2 67.56,86.96 42.06,86.96 30.6,98.42 30.6,108.9 29.56,109.94 28.99,109.94 28.29,110.64 28.29,111.67 v2(28.16,111.8)
  BOTTOM w0.203: U101.G11 v2(28.16,111.8)
DATA_CLK_P_B: length 84.8
  TOP w0.203: 80.63,16.14 v1(80,15.5)
  L5_SIG w0.097: v1(80,15.5) 79.74,15.76 78.59,15.76 77.22,17.13 75.29,17.13 75.04,17.38 75.04,19.63 74.91,19.75 73.55,19.75 73.42,19.63 73.42,17.38 73.18,17.13 52.13,17.13 44.22,25.04 44.05,25.04 43.08,24.08 43.08,23.9 48.68,18.29 48.68,17.9 47.57,16.79 47.18,16.79 33.7,30.26 28.73,30.26 28.49,30.02 28.49,29.81 28.25,29.56 27.7,29.56 27.34,29.2 26.86,29.2 v2(26.63,28.98)
  BOTTOM w0.203: U201.G11 v2(26.63,28.98)
DEBUG_1: length 1.2
  TOP w0.394: P401.C26 v1(86.88,111.49)
DEBUG_2: length 1.2
  TOP w0.394: P401.C27 85.71,112.78 v1(86.88,112.78)
DEBUG_3: length 1.2
  TOP w0.394: P402.C26 v1(86.88,41.54)
DEBUG_4: length 1.2
  TOP w0.394: v1(86.88,42.83) 85.71,42.83 P402.C27
EN_AGC_A: length 91.2
  TOP w0.394: P401.G27 v1(81.8,112.76)
  L5_SIG w0.124: P101.3 45.23,117.48 44.03,118.68 44.03,119.75 44.71,120.43 44.71,121.12 44.58,121.24 43.83,121.24 43.7,121.12 43.7,120.59 43.58,120.47 42.94,120.47 42.81,120.59 42.81,121.12 42.69,121.24 42.05,121.24 41.93,121.12 41.93,120.59 41.8,120.47 41.17,120.47 41.04,120.59 41.04,121.12 40.92,121.24 40.28,121.24 40.15,121.12 40.15,120.59 40.03,120.47 38.54,120.47 38.39,120.32 35.82,120.32 35.69,120.45 35.69,120.96 35.57,121.08 34.93,121.08 34.81,120.96 34.81,120.45 34.68,120.32 34.04,120.32 33.92,120.45 33.92,120.96 33.79,121.08 33.16,121.08 33.03,120.96 33.03,120.45 32.91,120.32 29.48,120.32 29.34,120.46 27.29,120.46 24.63,117.8 24.43,117.59 24.43,117.31 24.63,117.11 24.63,116.73 24.39,116.49 24.39,116.16 24.57,115.97 24.57,115.51 24.2,115.15 v2(24.2,114.62)
  L6_SIG w0.124: P101.3 45.23,115.82 45.55,115.5 64.29,115.5 65.34,114.44 72.93,114.44 73.05,114.32 73.05,113.73 73.18,113.6 73.81,113.6 73.94,113.73 73.94,114.32 74.06,114.44 74.7,114.44 74.82,114.32 74.82,113.75 74.95,113.62 75.58,113.62 75.71,113.75 75.71,114.32 75.83,114.44 76.47,114.44 76.6,114.32 76.6,112.89 76.72,112.76 77.53,112.76 77.66,112.89 77.66,113.34 77.78,113.47 79.08,113.47 79.21,113.34 79.21,111.75 79.34,111.62 80.06,111.62 80.19,111.75 80.19,113.36 80.31,113.48 80.99,113.48 81.11,113.36 81.11,109.82 81.24,109.69 82.09,109.69 82.21,109.82 82.21,112.61 82.06,112.76 v1(81.8,112.76)
  BOTTOM w0.254: v2(24.2,114.62) U101.G5
EN_AGC_B: length 90
  TOP w0.394: P402.G27 v1(81.8,42.81)
  L5_SIG w0.124: v2(23.81,25.02) 23.29,25.02 22.92,25.38 22.46,25.38 22.28,25.2 21.94,25.2 21.7,25.44 21.32,25.44 21.12,25.24 20.73,25.24 18.63,27.34 18.63,35.57 23.27,40.22 25.28,40.22 27.95,42.89 31.48,42.89 38.23,49.64 39.02,49.64 39.81,50.43 43.62,50.43 44.35,49.7 44.35,48.58 45.49,47.44 P201.3
  L6_SIG w0.124: v1(81.8,42.81) 79.44,42.81 78.86,43.39 77.08,43.39 76.2,44.27 64.05,44.27 62.97,45.35 46.87,45.35 P201.3
  BOTTOM w0.254: v2(23.81,25.02) U201.G5
ENABLE_A: length 89.1
  TOP w0.394: 80.63,101.33 v1(81.8,101.33)
  L5_SIG w0.124: v1(81.8,101.33) 81.95,101.18 81.95,100.77 81.82,100.65 81.14,100.65 79.98,101.8 77.26,101.8 76.82,102.25 76.82,103.54 76.51,103.85 75.39,103.85 75.15,104.09 75.15,105.97 71.98,109.14 51.94,109.14 51.82,109.27 51.82,109.79 51.69,109.92 47.69,109.92 47.46,110.15 47.46,113.77 47.23,114 43.98,114 43.77,114.22 43.77,115.62 P101.1 41.65,117.73 39.58,117.73 39.45,117.86 39.45,118.49 39.58,118.61 41.28,118.61 41.41,118.74 41.41,119.58 41.28,119.71 38.88,119.71 38.73,119.56 38.2,119.56 38.07,119.44 38.07,118.74 37.95,118.62 37.31,118.62 37.19,118.74 37.19,119.44 37.06,119.56 36.43,119.56 36.3,119.44 36.3,118.74 36.18,118.62 35.54,118.62 35.42,118.74 35.42,119.44 35.29,119.56 34.65,119.56 34.53,119.44 34.53,118.74 34.4,118.62 33.77,118.62 33.64,118.74 33.64,119.44 33.52,119.56 32.88,119.56 32.76,119.44 32.76,118.74 32.63,118.62 31.99,118.62 31.87,118.74 31.87,119.44 31.74,119.56 31.11,119.56 30.98,119.44 30.98,118.74 30.86,118.62 30.22,118.62 30.1,118.74 30.1,119.44 29.97,119.56 29.25,119.56 29.06,119.37 29.06,118.9 28.89,118.73 27.54,118.73 26.58,117.78 26.58,117.48 25.11,116.02 25.11,114.98 24.8,114.66 24.8,114.21 24.77,114.19 v2(24.77,114.06)
  BOTTOM w0.254: v2(24.77,114.06) U101.G6
ENABLE_B: length 89.7
  TOP w0.394: 80.63,31.38 v1(81.8,31.38)
  L5_SIG w0.124: v2(24.37,25.58) 24.24,25.58 24.22,25.61 23.77,25.61 23.46,25.92 22.42,25.92 20.95,27.39 20.66,27.39 19.69,28.35 19.69,35.06 23.22,38.6 29.17,38.6 33.08,42.51 40.34,42.51 40.7,42.86 40.7,46.27 41.16,46.73 P201.1 50.37,39.32 72.16,39.32 77.21,34.26 78.56,34.26 79.36,33.47 79.36,33.23 81.22,31.38 v1(81.8,31.38)
  BOTTOM w0.254: v2(24.37,25.58) U201.G6
FB_CLK_N_A: length 84.3
  TOP w0.203: v1(80.04,94.35) 80.04,94.39 80.63,94.98
  L5_SIG w0.097: v2(27.6,112.36) 27.46,112.22 27.46,112 27.84,111.62 27.84,110.69 29.31,109.22 29.31,97.69 40.9,86.1 56.12,86.1 56.95,85.26 66.88,85.26 67.79,86.16 77.3,86.16 78.52,84.95 80.46,84.95 80.71,85.2 80.71,94.24 80.53,94.42 80.11,94.42 v1(80.04,94.35)
  BOTTOM w0.203: U101.G10 v2(27.6,112.36)
FB_CLK_N_B: length 85.4
  TOP w0.203: v1(80.04,24.39) 80.63,24.98 80.63,25.03
  L5_SIG w0.097: v2(26.07,28.41) 26.47,28.41 26.71,28.65 27.74,28.65 28.81,29.72 32.49,29.72 46.37,15.84 67.54,15.84 68.04,16.34 77.12,16.34 78.49,14.96 80.3,14.96 80.98,15.64 83.77,15.64 83.9,15.77 83.9,17.8 83.77,17.93 80.9,17.93 80.63,18.21 80.63,20.04 80.9,20.32 84.01,20.32 84.14,20.44 84.14,21.59 84.01,21.72 80.95,21.72 80.67,21.99 80.67,24.25 80.53,24.39 v1(80.04,24.39)
  BOTTOM w0.203: U201.G10 v2(26.07,28.41)
FB_CLK_P_A: length 84.3
  TOP w0.203: 80.63,93.71 81.27,94.35 v1(81.31,94.35)
  L5_SIG w0.097: v1(81.31,94.35) 80.96,94 80.96,85.1 80.56,84.7 78.41,84.7 77.2,85.91 67.89,85.91 66.99,85.01 56.85,85.01 56.01,85.84 40.8,85.84 29.05,97.59 29.05,109.12 27.59,110.58 27.59,111.51 27.31,111.8 v2(27.03,111.8)
  BOTTOM w0.203: U101.F10 v2(27.03,111.8)
FB_CLK_P_B: length 85.4
  TOP w0.203: v1(81.31,24.39) 80.68,23.76 80.63,23.76
  L5_SIG w0.097: v1(81.31,24.39) 80.92,24 80.92,22.1 81.05,21.97 84.12,21.97 84.39,21.7 84.39,20.34 84.12,20.06 81.01,20.06 80.88,19.93 80.88,18.31 81.01,18.18 83.87,18.18 84.15,17.91 84.15,15.67 83.87,15.39 81.09,15.39 80.4,14.71 78.39,14.71 77.01,16.09 68.15,16.09 67.65,15.59 46.26,15.59 32.38,29.47 28.92,29.47 27.85,28.4 26.82,28.4 26.51,28.1 26.51,27.97 v2(26.63,27.84)
  BOTTOM w0.203: U201.F10 v2(26.63,27.84)
GA0: length 126.5
  TOP w0.254: v3(38.95,59.83) 38.69,59.58 38.69,51.88 37.94,51.13 U304.11
  TOP w0.394: P401.C34 v1(86.88,121.65)
  L5_SIG w0.124: v3(87.59,64.81) 90.83,68.05 90.83,116.38 88.86,118.35 88.86,120.28 87.49,121.65 v1(86.88,121.65)
  L6_SIG w0.124: v3(87.59,64.81) 86.8,65.6 81.03,65.6 74.2,58.76 64.42,58.76 63.51,59.68 57.67,59.68 56.75,58.76 40.57,58.76 39.5,59.83 v3(38.95,59.83)
  BOTTOM w0.305: v3(87.59,64.81) 87.68,64.9 U303.2
GA1: length 133.3
  TOP w0.254: v3(38.01,59.8) 36.94,58.74 U304.13
  TOP w0.394: 84.44,122.92 v1(83.28,122.92)
  L5_SIG w0.124: v1(83.28,122.92) 85.63,122.92 86.27,122.29 87.51,122.29 89.24,120.56 89.24,118.53 91.23,116.54 91.23,67.69 v3(88.33,64.79)
  L6_SIG w0.124: v3(88.33,64.79) 88.33,64.8 87.13,66 80.88,66 74.75,59.87 67.79,59.87 66.76,60.9 58.15,60.9 56.4,59.14 40.88,59.14 39.67,60.35 38.55,60.35 v3(38.01,59.8)
  BOTTOM w0.305: U303.1 v3(88.33,64.79)
GPO0_A: length 52.5
  L5_SIG w0.124: v2(23.08,110.23) 23.08,110.72 20.47,113.33 20.47,113.64 20.67,113.83 20.67,114.28 20.47,114.48 20.47,114.77 20.85,115.15 20.85,115.63 20.68,115.8 20.68,118.44 28.19,125.95 35.39,125.95 35.77,125.56 37.55,125.56 37.85,125.26 50.33,125.26 52.15,123.43 54.26,123.43 55.39,122.3 P101.12
  BOTTOM w0.254: v2(23.08,110.23) 23.08,110.41 23.08,110.66 U101.B7
GPO0_B: length 84.1
  L5_SIG w0.124: v2(28.2,23.89) 28.1,23.99 27.59,23.99 27.36,24.23 27.04,24.23 25.73,22.91 25.73,22.61 25.93,22.41 25.93,22.11 25.66,21.85 25.2,21.85 25.08,21.96 24.8,21.96 24.68,21.85 24.07,21.85 23.95,21.96 23.66,21.96 23.41,21.7 19.64,21.7 17.2,24.15 17.2,25.26 14.29,28.17 14.29,37.36 14.64,37.71 14.64,46.22 22.28,53.86 51.06,53.86 P201.12
  BOTTOM w0.254: U201.B7 27.77,23.89 28.02,23.89 v2(28.2,23.89)
GPO1_A: length 62.3
  L5_SIG w0.124: v2(22.51,110.79) 21.5,110.79 19.29,113 19.29,119.34 27.48,127.54 34.95,127.54 35.24,127.83 37.51,127.83 37.82,127.51 37.86,127.51 37.88,127.5 39.66,127.5 40.18,126.97 42.84,126.97 43.23,127.36 44.72,127.36 45.42,126.66 53.42,126.66 59.25,120.83 59.25,118.02 P101.13
  BOTTOM w0.254: U101.B6 22.51,110.8 v2(22.51,110.79)
GPO1_B: length 95.6
  L5_SIG w0.124: v2(27.64,23.32) 27.64,22.35 25.37,20.08 20.2,20.08 16.86,23.42 16.45,23.42 12.81,27.06 12.81,31.57 12.25,32.13 12.25,33.23 13.11,34.09 13.11,37.27 12.24,38.15 12.24,39.44 13.79,40.99 13.79,46.53 21.88,54.63 53.5,54.63 57.54,50.58 58.66,50.58 59.34,49.91 59.34,47.87 P201.13
  BOTTOM w0.254: U201.B6 27.63,23.32 v2(27.64,23.32)
GPO2_A: length 54.8
  L5_SIG w0.124: v2(21.38,111.8) 20.85,111.8 19.9,112.74 19.9,113.07 20.02,113.19 20.02,113.64 19.9,113.75 19.9,115.23 20.14,115.47 20.14,119.66 27.58,127.1 36.19,127.1 36.76,126.53 38.54,126.53 39.35,125.72 53.37,125.72 57.93,121.16 P101.14
  BOTTOM w0.254: v2(21.38,111.8) U101.B5
GPO2_B: length 87.1
  L5_SIG w0.124: v2(26.63,22.19) 26.63,21.7 26.21,21.28 25.93,21.28 25.81,21.4 25.36,21.4 25.24,21.28 24.8,21.28 24.68,21.4 24.21,21.4 23.76,20.94 19.87,20.94 16.82,23.99 16.82,25.11 13.19,28.74 13.19,31.73 13.19,31.73 12.63,32.28 12.63,33.07 13.6,34.03 13.6,37.35 13.11,37.83 13.11,38.49 14.17,39.55 14.17,46.3 22.11,54.24 53.22,54.24 P201.14
  BOTTOM w0.254: v2(26.63,22.19) U201.B5
GPO3_A: length 51.2
  L6_SIG w0.124: v2(20.81,112.36) 20.81,113.01 21.72,113.92 21.72,114.2 21.52,114.4 21.52,114.85 21.72,115.05 21.72,115.41 21.34,115.79 21.34,116.96 21.41,117.02 21.41,117.03 21.61,117.23 21.62,117.23 25.66,121.27 30.46,121.27 31.53,120.21 37.67,120.21 39.03,121.57 56.13,121.57 56.73,120.97 56.73,118.53 57.39,117.87 59.29,117.87 P101.15
  BOTTOM w0.254: v2(20.81,112.36) U101.B4
GPO3_B: length 83
  L6_SIG w0.124: v2(26.07,21.62) 25.42,21.62 24.51,22.53 24.23,22.53 24.03,22.33 23.58,22.33 23.38,22.53 23.1,22.53 22.9,22.33 22.23,22.33 20.85,23.71 19.87,23.71 17.58,26 17.58,39.54 16.97,40.14 16.97,46.97 23.23,53.22 56.88,53.22 59.41,50.7 59.41,48.06 P201.15
  BOTTOM w0.254: v2(26.07,21.62) U201.B4
PG_1P3_DIG_A: length 1.5
  TOP w0.305: U505.5 R511.1
PG_1P3_DIG_B: length 1.5
  TOP w0.305: R519.1 53.04,69.12 U507.5
PG_1P3_RF_A: length 1.5
  TOP w0.305: U504.5 R507.1
PG_1P3_RF_B: length 1.5
  TOP w0.305: U506.5 53.02,63.44 53.04,63.46 R515.1
PG_1P8V: length 18.2
  TOP w0.305: v3(54.85,75.15) 54.68,74.98 U505.4 ; v3(54.89,68.36) 54.72,68.19 U507.4 ; U506.4 53.96,61.4 v3(53.96,61.99) ; v3(54.86,81.97) 54.69,81.8 U504.4 ; U503.16 69.18,84.5 69.43,84.75
  TOP w0.394: 69.43,84.75 70.01,85.33 R504.1 70.01,88.05 v1(69.04,89.01) v1(69.04,89.9)
  BOTTOM w0.394: v3(54.85,75.15) 56.09,76.39 56.09,80.73 v3(54.86,81.97)
PG_FMC: length 36.1
  TOP w0.305: U501.3 v3(68.19,67.43) ; v3(70.04,83.53) 69.71,83.85 U503.15
  TOP w0.394: P401.D1 v1(83.28,79.74)
  L6_SIG w0.124: v1(83.28,79.74) 82.62,80.4 73.69,80.4 70.57,83.53 v3(70.04,83.53) 69.98,83.58 69.04,83.58 68.23,82.77 68.23,82.11 68.03,81.9 68.03,67.88 68.19,67.73 v3(68.19,67.43)
REF_CLK_FMC_N: length 103.7
  TOP w0.203: U301.14 17.86,68.74 17.95,68.83 18.62,68.83 v3(18.96,68.49)
  TOP w0.508: P401.D21 v1(83.28,105.14)
  L5_SIG w0.097: v3(18.96,68.49) 19.19,68.72 22.31,68.72 23.38,69.79 28.76,69.79 31.11,72.14 32.48,72.14 39.46,79.12 53.33,79.12 55.71,81.5 87.24,81.5 87.71,81.97 87.71,103 87.37,103.34 86.57,103.34 85.27,104.64 83.79,104.64 v1(83.28,105.14)
REF_CLK_FMC_P: length 103.7
  TOP w0.203: U301.15 17.86,69.24 17.92,69.18 18.58,69.18 v3(18.96,69.56)
  TOP w0.508: P401.D20 v1(83.28,103.87)
  L5_SIG w0.097: v1(83.28,103.87) 83.24,103.87 83.12,104 83.12,104.25 83.24,104.38 85.17,104.38 86.08,103.47 86.46,103.09 87.27,103.09 87.45,102.9 87.45,82.08 87.13,81.75 55.6,81.75 53.23,79.38 39.36,79.38 32.37,72.39 31.01,72.39 30.93,72.32 28.65,70.04 23.27,70.04 22.21,68.97 19.17,68.97 18.96,69.19 v3(18.96,69.56)
